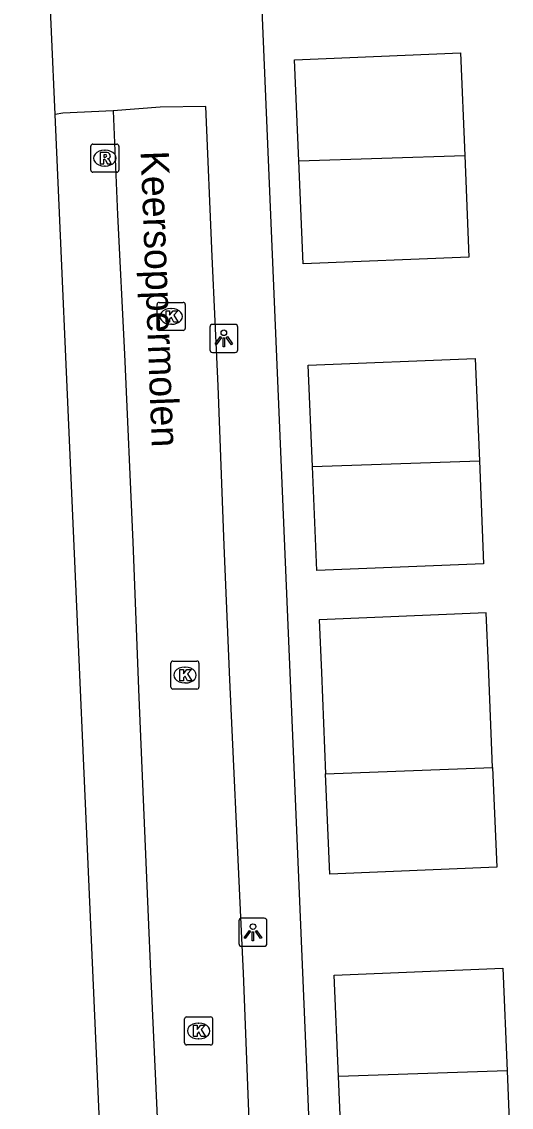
# Model space of a CAD drawing. Extents: x 161243 to 161752, y 384138 to 384885.
# Drawn here: x 161328.33 to 161345.76, y 384243.24 to 384281.86 of the extents above; entities that cross this region are included whole.
import ezdxf

# ---------------------------------------------------------------- set-up
doc = ezdxf.new("R2010")
doc.units = 0
for name, color, linetype in [('IMGEO_Kolk', 7, 'Continuous'), ('IMGEO_Lichtpunt', 7, 'Continuous'), ('IMGEO_Openbare_ruimte_label', 7, 'Continuous'), ('IMGEO_Pand', 7, 'Continuous'), ('IMGEO_Parkeervlak_open', 7, 'Continuous'), ('IMGEO_Rijbaan_lokaal_open', 7, 'Continuous'), ('IMGEO_Rioolput', 7, 'Continuous'), ('IMGEO_Voetpad_open', 7, 'Continuous')]:
    doc.layers.add(name, color=color, linetype=linetype)

msp = doc.modelspace()

# ---------------------------------------------------------------- linework, layer by layer
at = {"layer": 'IMGEO_Kolk'}
for p, q in [((161333.15, 384270.95), (161333.15, 384271.802)), ((161333.225, 384271.876), (161334.077, 384271.876)), ((161333.638, 384271.656), (161333.663, 384271.656)), ((161334.151, 384271.802), (161334.151, 384270.95)), ((161334.077, 384270.876), (161333.225, 384270.876)), ((161333.661, 384271.096), (161333.636, 384271.096)), ((161333.64, 384258.188), (161333.64, 384259.04)), ((161333.715, 384259.114), (161334.567, 384259.114)), ((161334.128, 384258.894), (161334.153, 384258.894)), ((161334.641, 384259.04), (161334.641, 384258.188)), ((161334.567, 384258.114), (161333.715, 384258.114)), ((161334.151, 384258.334), (161334.126, 384258.334)), ((161334.127, 384245.526), (161334.127, 384246.378)), ((161334.202, 384246.452), (161335.054, 384246.452)), ((161334.615, 384246.232), (161334.64, 384246.232)), ((161335.128, 384246.378), (161335.128, 384245.526)), ((161335.054, 384245.452), (161334.202, 384245.452)), ((161334.638, 384245.672), (161334.613, 384245.672))]:
    msp.add_line(p, q, dxfattribs=at)
for points in [[(161333.15, 384270.95), (161333.15, 384271.802)], [(161333.225, 384271.876), (161334.077, 384271.876)], [(161334.151, 384271.802), (161334.151, 384270.95)], [(161333.471, 384271.576), (161333.594, 384271.576), (161333.594, 384271.425), (161333.724, 384271.576), (161333.888, 384271.576), (161333.742, 384271.425), (161333.895, 384271.176), (161333.743, 384271.176), (161333.658, 384271.34), (161333.594, 384271.273), (161333.594, 384271.176), (161333.471, 384271.176), (161333.471, 384271.576)], [(161334.077, 384270.876), (161333.225, 384270.876)], [(161333.64, 384258.188), (161333.64, 384259.04)], [(161333.715, 384259.114), (161334.567, 384259.114)], [(161334.641, 384259.04), (161334.641, 384258.188)], [(161333.961, 384258.814), (161334.084, 384258.814), (161334.084, 384258.663), (161334.214, 384258.814), (161334.378, 384258.814), (161334.232, 384258.663), (161334.385, 384258.414), (161334.233, 384258.414), (161334.148, 384258.578), (161334.084, 384258.511), (161334.084, 384258.414), (161333.961, 384258.414), (161333.961, 384258.814)], [(161334.567, 384258.114), (161333.715, 384258.114)], [(161334.127, 384245.526), (161334.127, 384246.378)], [(161334.202, 384246.452), (161335.054, 384246.452)], [(161334.448, 384246.152), (161334.571, 384246.152), (161334.571, 384246.001), (161334.701, 384246.152), (161334.865, 384246.152), (161334.719, 384246.001), (161334.872, 384245.752), (161334.72, 384245.752), (161334.635, 384245.916), (161334.571, 384245.849), (161334.571, 384245.752), (161334.448, 384245.752), (161334.448, 384246.152)], [(161335.128, 384246.378), (161335.128, 384245.526)], [(161335.054, 384245.452), (161334.202, 384245.452)]]:
    msp.add_lwpolyline(points, dxfattribs=at)
for centre, start, end in [((161333.227, 384271.8), 91.552, 178.448), ((161333.227, 384271.8), 91.552, 178.448), ((161334.075, 384271.8), 1.552, 88.448), ((161334.075, 384271.8), 1.552, 88.448), ((161333.227, 384270.952), 181.552, 268.448), ((161333.227, 384270.952), 181.552, 268.448), ((161334.075, 384270.952), 271.552, 358.448), ((161334.075, 384270.952), 271.552, 358.448), ((161333.717, 384259.038), 91.552, 178.448), ((161333.717, 384259.038), 91.552, 178.448), ((161334.565, 384259.038), 1.552, 88.448), ((161334.565, 384259.038), 1.552, 88.448), ((161333.717, 384258.19), 181.552, 268.448), ((161333.717, 384258.19), 181.552, 268.448), ((161334.565, 384258.19), 271.552, 358.448), ((161334.565, 384258.19), 271.552, 358.448), ((161334.204, 384246.376), 91.552, 178.448), ((161334.204, 384246.376), 91.552, 178.448), ((161335.052, 384246.376), 1.552, 88.448), ((161335.052, 384246.376), 1.552, 88.448), ((161334.204, 384245.528), 181.552, 268.448), ((161334.204, 384245.528), 181.552, 268.448), ((161335.052, 384245.528), 271.552, 358.448), ((161335.052, 384245.528), 271.552, 358.448)]:
    msp.add_arc(centre, 0.0765, start, end, dxfattribs=at)
for centre, major_axis, ratio, start_param, end_param in [((161333.637, 384271.376), (-0.387, 0.002), 0.722429, 4.712389, 7.853982), ((161333.662, 384271.376), (-0.39, 0.002), 0.717154, 1.570796, 4.712389), ((161334.127, 384258.614), (-0.387, 0.002), 0.722429, 4.712389, 7.853982), ((161334.152, 384258.614), (-0.39, 0.002), 0.717154, 1.570796, 4.712389), ((161334.614, 384245.952), (-0.387, 0.002), 0.722429, 4.712389, 7.853982), ((161334.639, 384245.952), (-0.39, 0.002), 0.717154, 1.570796, 4.712389)]:
    msp.add_ellipse(centre, major_axis=major_axis, ratio=ratio, start_param=start_param, end_param=end_param, dxfattribs=at)
at = {"layer": 'IMGEO_Lichtpunt'}
for p, q in [((161335.028, 384270.996), (161335.028, 384270.189)), ((161335.028, 384270.996), (161335.028, 384270.189)), ((161335.93, 384271.091), (161335.122, 384271.091)), ((161335.93, 384271.091), (161335.122, 384271.091)), ((161336.024, 384270.189), (161336.024, 384270.996)), ((161336.024, 384270.189), (161336.024, 384270.996)), ((161335.122, 384270.095), (161335.93, 384270.095)), ((161335.122, 384270.095), (161335.93, 384270.095)), ((161336.062, 384249.867), (161336.062, 384249.06)), ((161336.062, 384249.867), (161336.062, 384249.06)), ((161336.964, 384249.962), (161336.156, 384249.962)), ((161336.964, 384249.962), (161336.156, 384249.962)), ((161337.058, 384249.06), (161337.058, 384249.867)), ((161337.058, 384249.06), (161337.058, 384249.867)), ((161336.156, 384248.966), (161336.964, 384248.966)), ((161336.156, 384248.966), (161336.964, 384248.966))]:
    msp.add_line(p, q, dxfattribs=at)
for points in [[(161335.402, 384270.66), (161335.441, 384270.632), (161335.253, 384270.37), (161335.215, 384270.397), (161335.402, 384270.66)], [(161335.504, 384270.612), (161335.551, 384270.612), (161335.551, 384270.29), (161335.504, 384270.29), (161335.504, 384270.612)], [(161335.614, 384270.632), (161335.652, 384270.659), (161335.839, 384270.397), (161335.8, 384270.369), (161335.614, 384270.632)], [(161336.436, 384249.531), (161336.475, 384249.503), (161336.287, 384249.241), (161336.249, 384249.268), (161336.436, 384249.531)], [(161336.538, 384249.483), (161336.585, 384249.483), (161336.585, 384249.161), (161336.538, 384249.161), (161336.538, 384249.483)], [(161336.648, 384249.503), (161336.686, 384249.53), (161336.873, 384249.268), (161336.834, 384249.24), (161336.648, 384249.503)]]:
    msp.add_lwpolyline(points, dxfattribs=at)
for centre in [(161335.527, 384270.794), (161336.561, 384249.665)]:
    msp.add_circle(centre, 0.0994, dxfattribs=at)
for centre, start, end in [((161335.122, 384270.996), 90, 180), ((161335.122, 384270.996), 90, 180), ((161335.93, 384270.996), 0, 90), ((161335.93, 384270.996), 0, 90), ((161335.122, 384270.189), 180, 270), ((161335.122, 384270.189), 180, 270), ((161335.93, 384270.189), 270, 0), ((161335.93, 384270.189), 270, 360), ((161336.156, 384249.867), 90, 180), ((161336.156, 384249.867), 90, 180), ((161336.964, 384249.867), 0, 90), ((161336.964, 384249.867), 0, 90), ((161336.156, 384249.06), 180, 270), ((161336.156, 384249.06), 180, 270), ((161336.964, 384249.06), 270, 0), ((161336.964, 384249.06), 270, 360)]:
    msp.add_arc(centre, 0.0946, start, end, dxfattribs=at)
at = {"layer": 'IMGEO_Pand'}
for points in [[(161338.195, 384276.914), (161338.045, 384280.511), (161343.947, 384280.757), (161344.1, 384277.099)], [(161344.1, 384277.099), (161344.25, 384273.49), (161338.348, 384273.245), (161338.195, 384276.914)], [(161338.195, 384276.914), (161344.1, 384277.099)], [(161338.683, 384266.04), (161338.533, 384269.637), (161344.471, 384269.884), (161344.623, 384266.235)], [(161344.623, 384266.235), (161344.775, 384262.578), (161338.837, 384262.331), (161338.683, 384266.04)], [(161338.683, 384266.04), (161344.623, 384266.235)], [(161345.094, 384255.324), (161344.943, 384258.953), (161344.865, 384260.834), (161338.919, 384260.586), (161338.997, 384258.705), (161339.147, 384255.098)], [(161339.147, 384255.098), (161345.094, 384255.324)], [(161345.094, 384255.324), (161345.241, 384251.782), (161339.296, 384251.534), (161339.147, 384255.098)], [(161339.611, 384244.328), (161339.457, 384247.935), (161345.452, 384248.191), (161345.608, 384244.531)], [(161345.608, 384244.531), (161345.759, 384240.988), (161339.764, 384240.732), (161339.611, 384244.328)], [(161345.608, 384244.531), (161339.611, 384244.328)]]:
    msp.add_lwpolyline(points, dxfattribs=at)
at = {"layer": 'IMGEO_Parkeervlak_open'}
msp.add_lwpolyline([(161329.121, 384207.854), (161328.33, 384226.87), (161331.708, 384226.956), (161331.483, 384232.641), (161332.229, 384232.66), (161332.238, 384232.98), (161332.074, 384232.979), (161331.97, 384235.447), (161332.105, 384235.442), (161332.113, 384235.728), (161331.409, 384235.703), (161330.784, 384250), (161329.521, 384278.565)], dxfattribs=at)
at = {"layer": 'IMGEO_Rijbaan_lokaal_open'}
for points in [[(161345.496, 384206.142), (161341.894, 384206.028), (161337.932, 384205.899), (161337.833, 384208.001), (161337.76, 384210.422), (161337.527, 384216.256), (161337.129, 384226.353), (161336.868, 384231.648), (161336.684, 384236.002), (161336.225, 384248.01), (161336.134, 384250), (161335.741, 384258.44), (161335.543, 384263.223), (161335.328, 384268.908), (161335.107, 384273.512), (161334.887, 384278.846), (161333.256, 384278.821), (161331.584, 384278.687)], [(161331.584, 384278.687), (161331.739, 384274.994), (161331.985, 384270.03), (161332.284, 384263.343), (161332.501, 384257.819), (161332.832, 384250), (161332.915, 384248.051), (161333.147, 384242.867), (161333.411, 384236.512), (161333.617, 384232.219), (161333.763, 384228.005), (161333.973, 384222.651), (161334.206, 384217.517), (161334.413, 384211.983), (161334.554, 384209.391), (161334.636, 384206.829), (161334.479, 384206.784)]]:
    msp.add_lwpolyline(points, dxfattribs=at)
at = {"layer": 'IMGEO_Rioolput'}
for p, q in [((161330.789, 384276.582), (161330.789, 384277.434)), ((161330.864, 384277.508), (161331.716, 384277.508)), ((161331.79, 384277.434), (161331.79, 384276.582)), ((161331.277, 384277.288), (161331.302, 384277.288)), ((161331.3, 384276.728), (161331.275, 384276.728)), ((161331.716, 384276.508), (161330.864, 384276.508))]:
    msp.add_line(p, q, dxfattribs=at)
for points in [[(161330.789, 384276.582), (161330.789, 384277.434)], [(161330.864, 384277.508), (161331.716, 384277.508)], [(161331.79, 384277.434), (161331.79, 384276.582)], [(161331.378, 384277.206), (161331.126, 384277.208), (161331.126, 384276.808)], [(161331.304, 384277.127), (161331.25, 384277.127), (161331.25, 384277.046)], [(161331.25, 384277.046), (161331.302, 384277.046)], [(161331.126, 384276.808), (161331.25, 384276.808), (161331.25, 384276.97), (161331.261, 384276.97)], [(161331.308, 384276.941), (161331.379, 384276.808), (161331.519, 384276.808), (161331.454, 384276.934)], [(161331.716, 384276.508), (161330.864, 384276.508)]]:
    msp.add_lwpolyline(points, dxfattribs=at)
for centre, radius, start, end in [((161330.866, 384277.432), 0.0765, 91.552, 178.448), ((161330.866, 384277.432), 0.0765, 91.552, 178.448), ((161331.714, 384277.432), 0.0765, 1.552, 88.448), ((161331.714, 384277.432), 0.0765, 1.552, 88.448), ((161331.286, 384277.235), 0.19, 274.7715, 282.9687), ((161331.31, 384277.031), 0.0964, 77.0061, 93.1865), ((161331.324, 384277.088), 0.0378, 276.6634, 79.6772), ((161331.377, 384277.096), 0.109, 350.3612, 89.416), ((161331.375, 384277.096), 0.112, 277.5842, 350.9817), ((161331.26, 384276.917), 0.0533, 26.0293, 88.6989), ((161331.359, 384276.881), 0.108, 29.5134, 73.7905), ((161330.866, 384276.584), 0.0765, 181.552, 268.448), ((161330.866, 384276.584), 0.0765, 181.552, 268.448), ((161331.714, 384276.584), 0.0765, 271.552, 358.448), ((161331.714, 384276.584), 0.0765, 271.552, 358.448)]:
    msp.add_arc(centre, radius, start, end, dxfattribs=at)
for centre, major_axis, ratio, start_param, end_param in [((161331.276, 384277.008), (-0.387, 0.002), 0.722429, 4.712389, 7.853982), ((161331.301, 384277.008), (-0.39, 0.002), 0.717154, 1.570796, 4.712389)]:
    msp.add_ellipse(centre, major_axis=major_axis, ratio=ratio, start_param=start_param, end_param=end_param, dxfattribs=at)
at = {"layer": 'IMGEO_Voetpad_open'}
for points in [[(161329.521, 384278.565), (161329.259, 384284.454)], [(161336.819, 384283.698), (161338.239, 384250), (161340.006, 384208.085), (161341.148, 384208.134)], [(161331.584, 384278.687), (161329.796, 384278.607), (161329.521, 384278.565)]]:
    msp.add_lwpolyline(points, dxfattribs=at)

# ---------------------------------------------------------------- texts
at = {"layer": 'IMGEO_Openbare_ruimte_label'}
msp.add_text('Keersoppermolen', height=1, rotation=272.1784, dxfattribs=at).set_placement((161332.563, 384277.254))

doc.saveas('drawing.dxf')
